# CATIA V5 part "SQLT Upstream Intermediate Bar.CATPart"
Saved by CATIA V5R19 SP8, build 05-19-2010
Part number: SQLT Upstream Intermediate Bar 26
Publications: "Droite.1", "Plan.1", "Plan.2", "Droite.2", "Droite.3", "Plan.3", "Plan.4"
Bounding box of the stored display mesh (mm): x -150 to 150, y 900 to 1000, z 400 to 500
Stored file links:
  G:\EU_thinkMotion\CFAO_2010\MMS_groupe3\MMS_groupe3\A reprendre\fovide\fovide\SQLT Upstream Intermediate Bar.CATPart
  G:\EU_thinkMotion\CFAO_2010\MMS_groupe3\MMS_groupe3\A reprendre\fovide\fovide\fovide.CATProduct
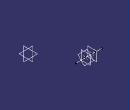
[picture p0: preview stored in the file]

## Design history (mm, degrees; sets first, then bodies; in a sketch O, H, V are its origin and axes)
Set1
  Point1 "Point.D": linked copy from another document
  Point2 "Point.F": linked copy from another document
Set2 "set Upstream Intermediate Bar"
  Line1: type PtPt, FirstPoint Point1, SecondPoint Point2
  Plane1: type OffsetPt, RefPlane yz-plane, RefPoint Point1
  Plane2: type OffsetPt, RefPlane yz-plane, RefPoint Point2
  Line2: type Normal, RefPoint Point1, RefSkin Plane1, Start -150, End 150
  Line3: type Normal, RefPoint Point2, RefSkin Plane2, Start -150, End 150
  Plane3: type Normal, Curve Line1, RefPoint Point2
  Plane4: type Angle, RefPlane Plane3, Direction Line3, Angle 90
Body1 (main body)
